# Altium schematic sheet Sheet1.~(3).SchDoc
size A4
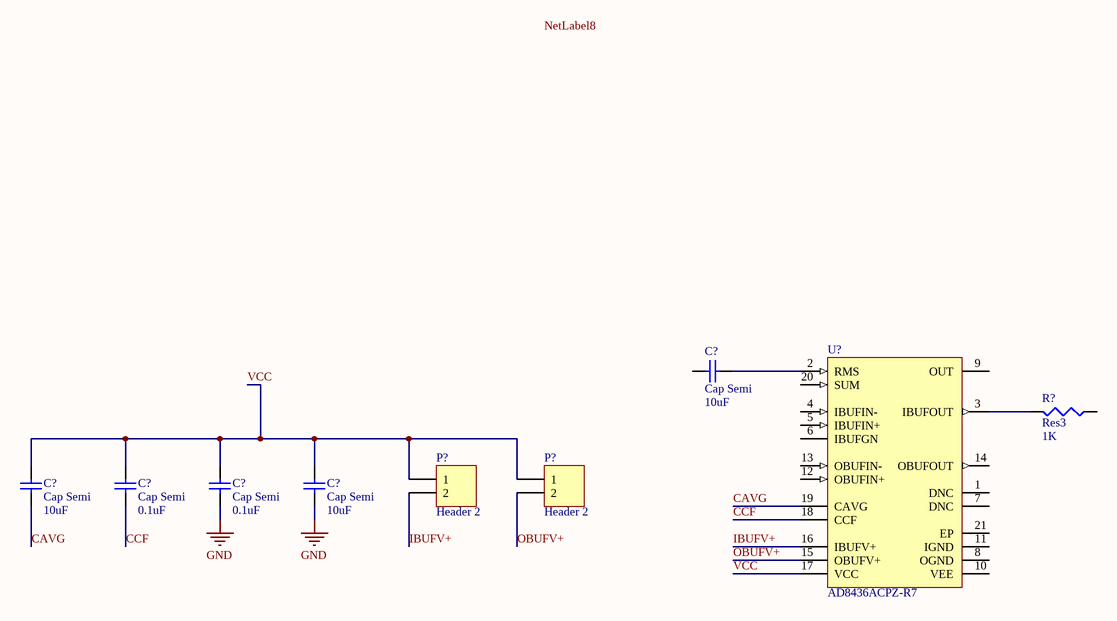
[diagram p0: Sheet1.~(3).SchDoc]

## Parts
(Parts that share a designator on the sheet are numbered #1, #2 ... from top to bottom, then left to right.)
C?#1  Cap Semi  value 10uF  [C1206]
C?#2  Cap Semi  value 10uF  [C1206]
C?#3  Cap Semi  value 0.1uF  [C1206]
C?#4  Cap Semi  value 0.1uF  [C1206]
C?#5  Cap Semi  value 10uF  [C1206]
P?#1  Header 2  [HDR1X2]
P?#2  Header 2  [HDR1X2]
R?  Res3  value 1K  [J1-0603]
U?  AD8436ACPZ-R7  [ADI-CP-20-10_M]

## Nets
GND: C?#4.1 C?#5.1
CAVG: C?#2.1 U?.19(CAVG)
CCF: C?#3.1 U?.18(CCF)
IBUFV+: P?#1.2 U?.16(IBUFV+)
OBUFV+: P?#2.2 U?.15(OBUFV+)
VCC: C?#2.2 C?#3.2 C?#4.2 C?#5.2 P?#1.1 P?#2.1 U?.17(VCC)
NetC?#1_2: C?#1.2 U?.2(RMS)
NetR?_2: R?.2 U?.3(IBUFOUT)

Not connected (* = marked no-connect by the designer): C?#1 1; R? 1; U? 1(DNC) 4(IBUFIN-) 5(IBUFIN+) 6(IBUFGN) 7(DNC) 8(OGND) 9(OUT) 10(VEE) 11(IGND) 12(OBUFIN+) 13(OBUFIN-) 14(OBUFOUT) 20(SUM) 21(EP)

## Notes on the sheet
- Labels drawn without touching a wire or pin: NetLabel8

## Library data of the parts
C?#1-C?#5 = Cap Semi: Capacitor (Semiconductor SIM Model)
P?#1 P?#2 = Header 2: Header, 2-Pin
R? = Res3: Resistor
U? = CMP-0527-00003-3: Low Cost, Low Power, True RMS-to-DC Converter, 4.8 to 36 V Single Supply, -40 to 125 degC, 20-Pin QFN (CP-20-10); Manufacturer: Analog Devices; -3dB Bandwidth: 950 KHz; Max Vin (V-rms): 3 V rms; V Span (min): 4.8 V; Supply Current: 300 uA; V Span (max): 36 V; Error (%@ CF: 3)=0.5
